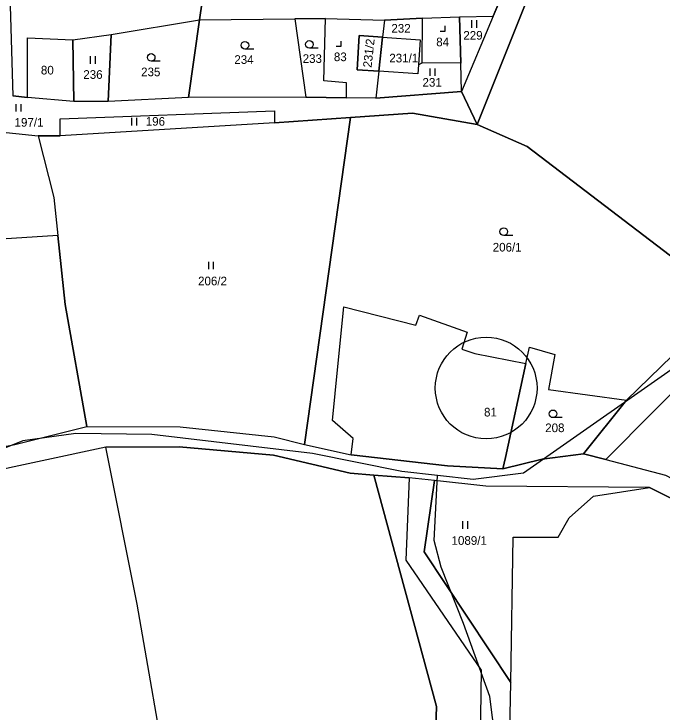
# Model space of a CAD drawing. Extents: x -588699 to -585793, y -1060280 to -1056731.
# Drawn here: x -587820.9 to -587693.5, y -1058364.5 to -1058227.3 of the extents above; entities that cross this region are included whole.
import ezdxf

# ---------------------------------------------------------------- set-up
doc = ezdxf.new("R2010")
doc.units = 0
for name, color, linetype in [('Druh pozemku', 7, 'Continuous'), ('Lesy', 7, 'Continuous'), ('Parcela nároku', 7, 'Continuous'), ('Stavby', 7, 'Continuous'), ('Vnitřní obvod', 7, 'Continuous')]:
    doc.layers.add(name, color=color, linetype=linetype)

msp = doc.modelspace()

# ---------------------------------------------------------------- linework, layer by layer
at = {"layer": 'Druh pozemku'}
for p, q in [((-587730.96, -1058228.46), (-587730.96, -1058229.96)), ((-587729.94, -1058229.96), (-587729.94, -1058228.46)), ((-587773.78, -1058234.16), (-587775.53, -1058234.16)), ((-587761.1, -1058234), (-587762.85, -1058234)), ((-587805.93, -1058235.55), (-587805.93, -1058237.05)), ((-587804.91, -1058237.05), (-587804.91, -1058235.55)), ((-587792.21, -1058236.55), (-587793.96, -1058236.55)), ((-587739.16, -1058237.96), (-587739.16, -1058239.46)), ((-587738.14, -1058239.46), (-587738.14, -1058237.96)), ((-587820.55, -1058244.97), (-587820.55, -1058246.47)), ((-587819.53, -1058246.47), (-587819.53, -1058244.97)), ((-587797.82, -1058247.68), (-587797.82, -1058249.18)), ((-587796.8, -1058249.18), (-587796.8, -1058247.68)), ((-587722.86, -1058270.81), (-587724.61, -1058270.81)), ((-587782.72, -1058275.96), (-587782.72, -1058277.46)), ((-587781.7, -1058277.46), (-587781.7, -1058275.96)), ((-587713.16, -1058306.62), (-587714.91, -1058306.62)), ((-587732.72, -1058326.96), (-587732.72, -1058328.46)), ((-587731.7, -1058328.46), (-587731.7, -1058326.96))]:
    msp.add_line(p, q, dxfattribs=at)
for points in [[(-587737.15, -1058230.63), (-587736.15, -1058230.63), (-587736.15, -1058229.63)], [(-587757.58, -1058233.61), (-587756.58, -1058233.61), (-587756.58, -1058232.61)]]:
    msp.add_lwpolyline(points, dxfattribs=at)
for centre in [(-587762.85, -1058233.25), (-587775.53, -1058233.41), (-587793.96, -1058235.8), (-587724.61, -1058270.06), (-587714.91, -1058305.87)]:
    msp.add_circle(centre, 0.75, dxfattribs=at)
at = {"layer": 'Lesy'}
for p, q in [((-587720.49, -1058212.9), (-587726.73, -1058227.72)), ((-587726.73, -1058227.72), (-587732.95, -1058242.49)), ((-587818.31, -1058243.66), (-587821.15, -1058243.34)), ((-587732.95, -1058242.49), (-587749.8, -1058243.84)), ((-587809.19, -1058244.46), (-587818.31, -1058243.66)), ((-587802.39, -1058244.46), (-587809.19, -1058244.46)), ((-587786.6, -1058243.69), (-587802.39, -1058244.46)), ((-587763.52, -1058243.59), (-587786.6, -1058243.69)), ((-587755.57, -1058243.72), (-587763.52, -1058243.59)), ((-587749.8, -1058243.84), (-587755.57, -1058243.72))]:
    msp.add_line(p, q, dxfattribs=at)
at = {"layer": 'Parcela nároku'}
for points in [[(-587725.77, -1058213.98), (-587725.94, -1058209.85), (-587719.82, -1058201.93), (-587717.78, -1058196.52), (-587754.65, -1058182.79), (-587754.36, -1058180.78), (-587776.54, -1058173.02), (-587782.05, -1058211.71), (-587784.43, -1058228.44), (-587765.7, -1058228.21), (-587759.68, -1058228.13), (-587748.07, -1058228.46), (-587740.57, -1058228.12), (-587733.31, -1058227.8), (-587726.73, -1058227.72), (-587720.49, -1058212.9)], [(-587726.73, -1058227.72), (-587732.95, -1058242.49), (-587729.82, -1058248.97), (-587717.53, -1058218.16), (-587708.93, -1058201.78), (-587706.46, -1058185.75), (-587711.77, -1058183.47), (-587714.16, -1058197.87), (-587720.49, -1058212.9)], [(-587700.35, -1058199.17), (-587701.75, -1058199.02), (-587702.14, -1058202.49), (-587708.93, -1058201.78), (-587717.53, -1058218.16), (-587729.82, -1058248.97), (-587719.99, -1058253.31), (-587674.16, -1058288.28), (-587646.41, -1058281.16), (-587640.42, -1058275.85), (-587635.5, -1058262.73), (-587628.39, -1058236.86), (-587631.42, -1058228.44), (-587642.62, -1058218.23), (-587676.1, -1058196.56), (-587686.68, -1058191.64), (-587696.89, -1058208.97), (-587701.04, -1058207.1)], [(-587782.05, -1058211.71), (-587785.66, -1058210.74), (-587807.31, -1058208.75), (-587808.84, -1058212.5), (-587818.5, -1058212.03), (-587820.04, -1058210.7), (-587822.07, -1058212.23), (-587821.15, -1058243.34), (-587818.31, -1058243.66), (-587818.31, -1058231.95), (-587809.37, -1058232.33), (-587801.84, -1058231.28), (-587784.43, -1058228.44)], [(-587801.84, -1058231.28), (-587784.43, -1058228.44), (-587786.6, -1058243.69), (-587802.39, -1058244.46)], [(-587765.7, -1058228.21), (-587763.52, -1058243.59), (-587786.6, -1058243.69), (-587784.43, -1058228.44)], [(-587755.57, -1058240.79), (-587759.99, -1058240.43), (-587759.68, -1058228.13), (-587765.7, -1058228.21), (-587763.52, -1058243.59), (-587755.57, -1058243.72)], [(-587759.99, -1058240.43), (-587759.68, -1058228.13), (-587748.07, -1058228.46), (-587748.45, -1058231.83), (-587753.03, -1058231.53), (-587753.47, -1058238.24), (-587749.2, -1058238.52), (-587749.8, -1058243.84), (-587755.57, -1058243.72), (-587755.57, -1058240.79)], [(-587741.06, -1058232.32), (-587741.38, -1058237.25), (-587740.64, -1058236.87), (-587740.57, -1058228.12), (-587748.07, -1058228.46), (-587748.45, -1058231.83)], [(-587740.64, -1058236.87), (-587740.57, -1058228.12), (-587733.31, -1058227.8), (-587733.09, -1058236.91)], [(-587733.31, -1058227.8), (-587726.73, -1058227.72), (-587732.95, -1058242.49), (-587733.09, -1058236.91)], [(-587818.31, -1058231.95), (-587809.37, -1058232.33), (-587809.19, -1058244.46), (-587818.31, -1058243.66)], [(-587809.37, -1058232.33), (-587801.84, -1058231.28), (-587802.39, -1058244.46), (-587809.19, -1058244.46)], [(-587753.47, -1058238.24), (-587753.03, -1058231.53), (-587748.45, -1058231.83), (-587749.2, -1058238.52)], [(-587748.45, -1058231.83), (-587741.06, -1058232.32), (-587741.38, -1058237.25), (-587741.49, -1058239.02), (-587749.2, -1058238.52)], [(-587733.09, -1058236.91), (-587740.64, -1058236.87), (-587741.38, -1058237.25), (-587741.49, -1058239.02), (-587749.2, -1058238.52), (-587749.8, -1058243.84), (-587732.95, -1058242.49)], [(-587811.86, -1058251.2), (-587811.86, -1058247.9), (-587769.71, -1058246.29), (-587769.73, -1058248.67)], [(-587813.08, -1058263.36), (-587812.29, -1058270.81), (-587888.36, -1058275.75), (-587886.36, -1058253.87), (-587852.04, -1058247.5), (-587816.19, -1058251.23)], [(-587811.86, -1058251.2), (-587816.19, -1058251.23), (-587813.08, -1058263.36), (-587812.29, -1058270.81), (-587810.86, -1058284.41), (-587806.59, -1058308.33), (-587788.26, -1058308.45), (-587769.75, -1058310.37), (-587763.78, -1058311.91), (-587754.76, -1058247.63), (-587769.73, -1058248.67)], [(-587714.56, -1058294.23), (-587715.83, -1058301.09), (-587700.47, -1058303.18), (-587689.18, -1058292.21), (-587684, -1058289.33), (-587674.16, -1058288.28), (-587719.99, -1058253.31), (-587729.82, -1058248.97), (-587742.6, -1058246.79), (-587754.76, -1058247.63), (-587763.78, -1058311.91), (-587754.65, -1058313.93), (-587754.21, -1058310.74), (-587758.28, -1058307.21), (-587757.75, -1058301.87), (-587756.24, -1058286.72), (-587756.05, -1058284.81), (-587741.89, -1058288.46), (-587741.17, -1058286.45), (-587731.83, -1058289.83), (-587732.89, -1058293.18), (-587730.3, -1058294.02), (-587720.27, -1058295.95), (-587719.58, -1058292.75)], [(-587812.29, -1058270.81), (-587888.36, -1058275.75), (-587889.04, -1058296.56), (-587883.78, -1058296.46), (-587884.12, -1058325.43), (-587882.85, -1058325.77), (-587861.42, -1058325.37), (-587847.92, -1058320.82), (-587830.54, -1058313.79), (-587820.75, -1058311.88), (-587806.59, -1058308.33), (-587810.86, -1058284.41)], [(-587700.47, -1058303.18), (-587689.18, -1058292.21), (-587684, -1058289.33), (-587674.16, -1058288.28), (-587646.41, -1058281.16), (-587638.55, -1058279.41), (-587612.73, -1058275.75), (-587609.81, -1058278.22), (-587639.72, -1058282.27), (-587640.85, -1058284.02), (-587646.17, -1058283.89), (-587672.5, -1058290.86), (-587678.75, -1058295.56), (-587685.58, -1058295.75), (-587704.55, -1058314.88), (-587708.91, -1058313.76)], [(-587741.89, -1058288.46), (-587741.17, -1058286.45), (-587731.83, -1058289.83), (-587732.89, -1058293.18), (-587730.3, -1058294.02), (-587720.27, -1058295.95), (-587724.28, -1058314.44), (-587724.77, -1058316.71), (-587735.7, -1058316.07), (-587754.65, -1058313.93), (-587754.21, -1058310.74), (-587758.28, -1058307.21), (-587757.75, -1058301.87), (-587756.24, -1058286.72), (-587756.05, -1058284.81)], [(-587724.77, -1058316.71), (-587724.28, -1058314.44), (-587720.27, -1058295.95), (-587719.58, -1058292.75), (-587714.56, -1058294.23), (-587715.83, -1058301.09), (-587700.47, -1058303.18), (-587708.91, -1058313.76), (-587717.04, -1058314.79)], [(-587645.89, -1058310.93), (-587678.75, -1058295.56), (-587685.58, -1058295.75), (-587704.55, -1058314.88), (-587692.8, -1058317.92), (-587639.67, -1058345.81), (-587642.99, -1058328.31)], [(-587750.15, -1058317.91), (-587743.2, -1058318.43), (-587743.91, -1058334.62), (-587729.06, -1058356.27), (-587731.34, -1058514.59), (-587741.94, -1058488.97), (-587737.84, -1058363.4)], [(-587728.17, -1058320.12), (-587738.24, -1058318.96), (-587740.26, -1058333.03), (-587723.26, -1058358.68), (-587722.78, -1058330.1), (-587713.89, -1058330.1), (-587711.77, -1058326.33), (-587706.96, -1058322.08), (-587695.94, -1058320.38)]]:
    msp.add_lwpolyline(points, close=True, dxfattribs=at)
for points in [[(-587852.04, -1058247.5), (-587816.19, -1058251.23), (-587811.86, -1058251.2), (-587811.86, -1058247.9), (-587769.71, -1058246.29), (-587769.73, -1058248.67), (-587754.76, -1058247.63), (-587742.6, -1058246.79), (-587729.82, -1058248.97), (-587732.95, -1058242.49), (-587749.8, -1058243.84), (-587755.57, -1058243.72), (-587763.52, -1058243.59), (-587786.6, -1058243.69), (-587802.39, -1058244.46), (-587809.19, -1058244.46), (-587818.31, -1058243.66), (-587821.15, -1058243.34)], [(-587830.54, -1058313.79), (-587820.75, -1058311.88), (-587806.59, -1058308.33), (-587788.26, -1058308.45), (-587769.75, -1058310.37), (-587763.78, -1058311.91), (-587754.65, -1058313.93), (-587735.7, -1058316.07), (-587724.77, -1058316.71), (-587717.04, -1058314.79), (-587708.91, -1058313.76), (-587704.55, -1058314.88), (-587692.8, -1058317.92), (-587639.67, -1058345.81), (-587633.64, -1058348.33), (-587630.7, -1058349.56), (-587614.01, -1058356.52), (-587591.38, -1058368.57)], [(-587847.1, -1058678.18), (-587805.8, -1058562.87), (-587793.34, -1058528.74), (-587773.66, -1058473.44), (-587773.44, -1058458.97), (-587777.44, -1058435.55), (-587782.36, -1058412.87), (-587790.37, -1058379.82), (-587796.73, -1058343.29), (-587802.9, -1058312.42), (-587788.47, -1058312.37), (-587769.93, -1058314.02), (-587754.84, -1058317.56), (-587750.15, -1058317.91), (-587737.84, -1058363.4), (-587741.94, -1058488.97), (-587731.34, -1058514.59), (-587731.38, -1058579.13), (-587741.35, -1058618.05), (-587757.52, -1058664.04), (-587794, -1058713.14), (-587812.7, -1058735.14), (-587832.62, -1058767.34)], [(-587847.1, -1058678.18), (-587805.8, -1058562.87), (-587793.34, -1058528.74), (-587773.66, -1058473.44), (-587773.44, -1058458.97), (-587777.44, -1058435.55), (-587782.36, -1058412.87), (-587790.37, -1058379.82), (-587796.73, -1058343.29), (-587802.9, -1058312.42), (-587827.99, -1058317.83)], [(-587592.13, -1058372.84), (-587613.98, -1058359.18), (-587631.34, -1058352.01), (-587634.55, -1058350.69), (-587639.64, -1058348.59), (-587695.94, -1058320.38), (-587728.17, -1058320.12), (-587738.24, -1058318.96), (-587743.2, -1058318.43), (-587750.15, -1058317.91), (-587754.84, -1058317.56), (-587769.93, -1058314.02), (-587788.47, -1058312.37), (-587802.9, -1058312.42), (-587827.99, -1058317.83)], [(-587828.97, -1058768.29), (-587810.6, -1058738.41), (-587795.75, -1058721.48), (-587753.66, -1058665.42), (-587737.19, -1058617.25), (-587726.96, -1058577.41), (-587725.51, -1058469.33), (-587723.26, -1058358.68), (-587740.26, -1058333.03), (-587738.24, -1058318.96), (-587743.2, -1058318.43), (-587743.91, -1058334.62), (-587729.06, -1058356.27), (-587731.34, -1058514.59), (-587731.38, -1058579.13), (-587741.35, -1058618.05), (-587757.52, -1058664.04), (-587794, -1058713.14), (-587812.7, -1058735.14), (-587832.62, -1058767.34)], [(-587737.19, -1058617.25), (-587726.96, -1058577.41), (-587725.51, -1058469.33), (-587723.26, -1058358.68), (-587722.78, -1058330.1), (-587713.89, -1058330.1), (-587711.77, -1058326.33), (-587706.96, -1058322.08), (-587695.94, -1058320.38), (-587639.64, -1058348.59), (-587638.99, -1058362.02), (-587635.81, -1058396.35), (-587625.09, -1058428.31), (-587624.61, -1058487.07), (-587628.3, -1058517.38), (-587632.21, -1058540.26), (-587647.07, -1058584.65), (-587664.66, -1058630.41)]]:
    msp.add_lwpolyline(points, dxfattribs=at)
at = {"layer": 'Stavby'}
msp.add_circle((-587728.08, -1058300.8), 10, dxfattribs=at)
at = {"layer": 'Vnitřní obvod'}
for points in [[(-587618.32, -1058235.21), (-587619.24, -1058241.84), (-587630.12, -1058261.43), (-587639.03, -1058275.05), (-587648.29, -1058282.31), (-587687.11, -1058294.03), (-587720.76, -1058317.55), (-587730.61, -1058318.77), (-587744.69, -1058317.23), (-587762.22, -1058313.68), (-587793.8, -1058309.93), (-587808.78, -1058309.77), (-587819.19, -1058311.15), (-587832.86, -1058316.6)], [(-587823.2, -1058767.71), (-587808.06, -1058745.23), (-587799.92, -1058733.14), (-587789.97, -1058715.46), (-587785.82, -1058706.67), (-587778.72, -1058691.63), (-587771.81, -1058680.4), (-587762.5, -1058665.27), (-587757.57, -1058655.27), (-587748.69, -1058634.1), (-587738.62, -1058604.99), (-587733.8, -1058587.38), (-587730.51, -1058572.57), (-587729.07, -1058558.28), (-587726.53, -1058499.07), (-587726.23, -1058479.5), (-587725.78, -1058450.42), (-587724.97, -1058397.82), (-587725.71, -1058374.37), (-587727.34, -1058361.42), (-587732.55, -1058347.08), (-587736.95, -1058336.01), (-587738.33, -1058330.74), (-587737.65, -1058318)]]:
    msp.add_lwpolyline(points, dxfattribs=at)

# ---------------------------------------------------------------- texts
at = {"layer": 'Parcela nároku'}
for s, p in [('232', (-587746.72, -1058230.94)), ('229', (-587732.57, -1058232.32)), ('84', (-587737.9, -1058233.62)), ('234', (-587777.61, -1058237.08)), ('233', (-587764.17, -1058236.89)), ('83', (-587758.03, -1058236.54)), ('231/1', (-587747.13, -1058236.79)), ('80', (-587815.65, -1058239.16)), ('235', (-587795.94, -1058239.51)), ('236', (-587807.31, -1058240.02)), ('231', (-587740.6, -1058241.56)), ('197/1', (-587820.83, -1058249.42)), ('196', (-587795.03, -1058249.23)), ('206/1', (-587726.79, -1058273.97)), ('206/2', (-587784.74, -1058280.61)), ('81', (-587728.5, -1058306.39)), ('208', (-587716.47, -1058309.47)), ('1089/1', (-587734.89, -1058331.62))]:
    msp.add_text(s, height=1.7, dxfattribs=at).set_placement(p)
msp.add_text('231/2', height=1.7, rotation=83.6798, dxfattribs=at).set_placement((-587750.63, -1058237.89))

doc.saveas('drawing.dxf')
